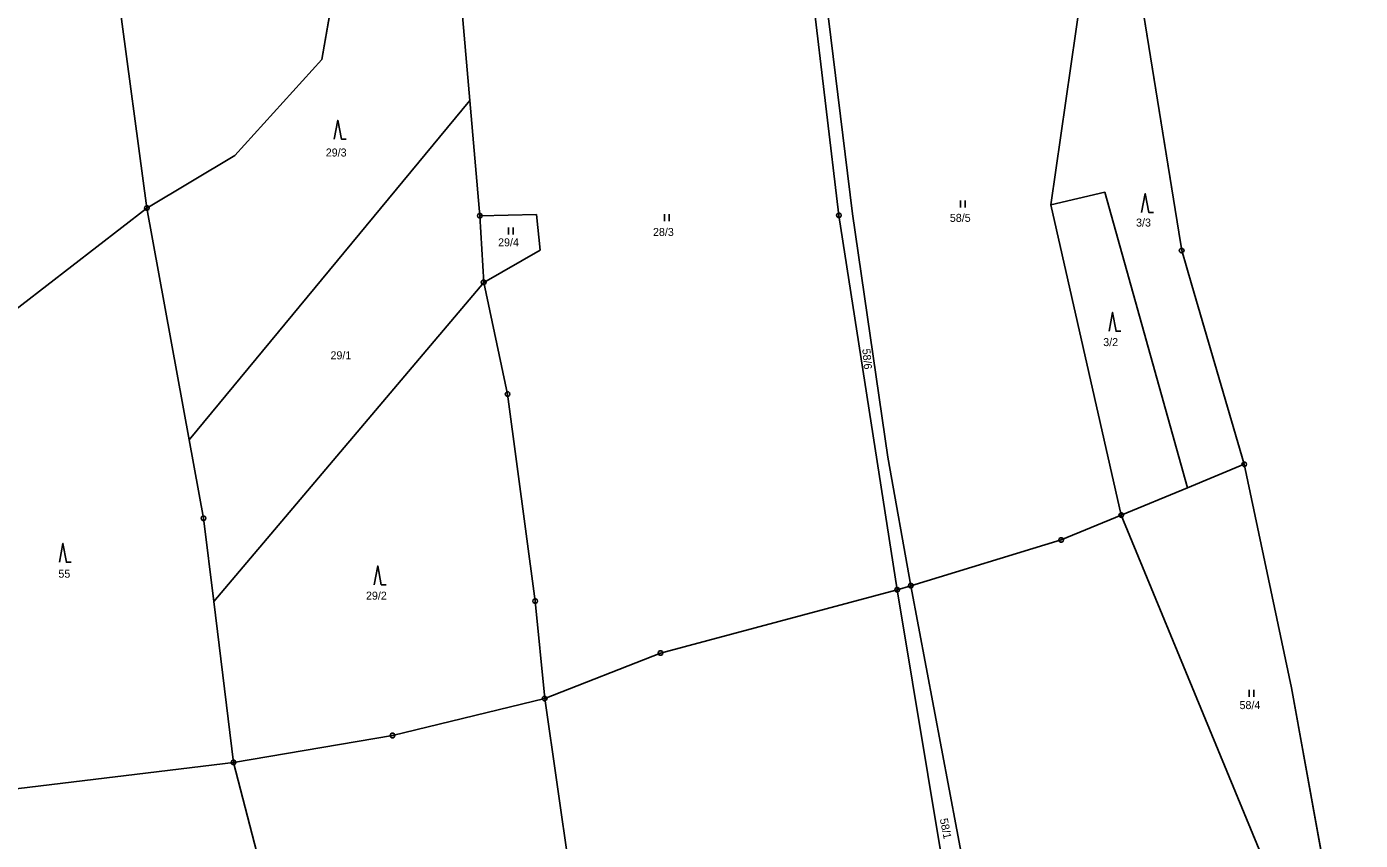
# Model space of a CAD drawing. Extents: x -580551 to -575069, y -1073031 to -1067931.
# Drawn here: x -576638.6 to -576355.3, y -1069440.4 to -1069267.5 of the extents above; entities that cross this region are included whole.
import ezdxf

# ---------------------------------------------------------------- set-up
doc = ezdxf.new("R2010")
doc.units = 0
for name, color, linetype in [('Druh pozemku', 7, 'Continuous'), ('Geodetické body', 7, 'Continuous'), ('Hranice obcí', 7, 'Continuous'), ('Hranice z DKM', 7, 'Continuous'), ('Katastrální hranice', 7, 'Continuous'), ('Parcela', 7, 'Continuous'), ('Parcelní číslo', 7, 'Continuous')]:
    doc.layers.add(name, color=color, linetype=linetype)

msp = doc.modelspace()

# ---------------------------------------------------------------- linework, layer by layer
at = {"layer": 'Druh pozemku'}
for p, q in [((-576440.24, -1069304.47), (-576440.24, -1069305.97)), ((-576439.24, -1069305.97), (-576439.24, -1069304.47)), ((-576503.17, -1069307.34), (-576503.17, -1069308.84)), ((-576502.17, -1069308.84), (-576502.17, -1069307.34)), ((-576536.3, -1069310.19), (-576536.3, -1069311.69)), ((-576535.3, -1069311.69), (-576535.3, -1069310.19)), ((-576378.97, -1069408.45), (-576378.97, -1069409.95)), ((-576377.97, -1069409.95), (-576377.97, -1069408.45))]:
    msp.add_line(p, q, dxfattribs=at)
for points in [[(-576573.28, -1069291.41), (-576572.53, -1069287.41), (-576571.78, -1069291.41), (-576570.78, -1069291.41)], [(-576401.78, -1069307), (-576401.03, -1069303), (-576400.28, -1069307), (-576399.28, -1069307)], [(-576408.71, -1069332.26), (-576407.96, -1069328.26), (-576407.21, -1069332.26), (-576406.21, -1069332.26)], [(-576631.67, -1069381.32), (-576630.92, -1069377.32), (-576630.17, -1069381.32), (-576629.17, -1069381.32)], [(-576564.79, -1069386.11), (-576564.04, -1069382.11), (-576563.29, -1069386.11), (-576562.29, -1069386.11)]]:
    msp.add_lwpolyline(points, dxfattribs=at)
at = {"layer": 'Geodetické body'}
for p, q in [((-576613.2, -1069306.06), (-576612.96, -1069306.06)), ((-576542.47, -1069307.7), (-576542.23, -1069307.7)), ((-576466.2, -1069307.62), (-576465.96, -1069307.62)), ((-576393.4, -1069315.11), (-576393.16, -1069315.11)), ((-576541.66, -1069321.86), (-576541.42, -1069321.86)), ((-576536.58, -1069345.6), (-576536.34, -1069345.6)), ((-576380.1, -1069360.52), (-576379.86, -1069360.52)), ((-576406.23, -1069371.32), (-576405.99, -1069371.32)), ((-576601.17, -1069371.99), (-576600.93, -1069371.99)), ((-576419, -1069376.59), (-576418.76, -1069376.59)), ((-576453.83, -1069387.19), (-576453.59, -1069387.19)), ((-576450.92, -1069386.31), (-576450.68, -1069386.31)), ((-576530.74, -1069389.59), (-576530.5, -1069389.59)), ((-576504.1, -1069400.63), (-576503.86, -1069400.63)), ((-576528.71, -1069410.32), (-576528.47, -1069410.32)), ((-576561.03, -1069418.15), (-576560.79, -1069418.15)), ((-576594.82, -1069423.88), (-576594.58, -1069423.88))]:
    msp.add_line(p, q, dxfattribs=at)
for points in [[(-576612.93, -1069305.58), (-576612.68, -1069305.76), (-576612.58, -1069306.05), (-576612.68, -1069306.34), (-576612.93, -1069306.52), (-576613.24, -1069306.52), (-576613.49, -1069306.34), (-576613.59, -1069306.05), (-576613.49, -1069305.76), (-576613.24, -1069305.58)], [(-576542.2, -1069307.22), (-576541.95, -1069307.4), (-576541.85, -1069307.69), (-576541.95, -1069307.98), (-576542.2, -1069308.16), (-576542.51, -1069308.16), (-576542.76, -1069307.98), (-576542.86, -1069307.69), (-576542.76, -1069307.4), (-576542.51, -1069307.22)], [(-576465.93, -1069307.14), (-576465.68, -1069307.32), (-576465.58, -1069307.61), (-576465.68, -1069307.9), (-576465.93, -1069308.08), (-576466.24, -1069308.08), (-576466.49, -1069307.9), (-576466.59, -1069307.61), (-576466.49, -1069307.32), (-576466.24, -1069307.14)], [(-576393.13, -1069314.63), (-576392.88, -1069314.81), (-576392.78, -1069315.1), (-576392.88, -1069315.39), (-576393.13, -1069315.57), (-576393.44, -1069315.57), (-576393.69, -1069315.39), (-576393.79, -1069315.1), (-576393.69, -1069314.81), (-576393.44, -1069314.63)], [(-576541.39, -1069321.38), (-576541.14, -1069321.56), (-576541.04, -1069321.85), (-576541.14, -1069322.14), (-576541.39, -1069322.32), (-576541.7, -1069322.32), (-576541.95, -1069322.14), (-576542.05, -1069321.85), (-576541.95, -1069321.56), (-576541.7, -1069321.38)], [(-576536.31, -1069345.12), (-576536.06, -1069345.3), (-576535.96, -1069345.59), (-576536.06, -1069345.88), (-576536.31, -1069346.06), (-576536.62, -1069346.06), (-576536.87, -1069345.88), (-576536.97, -1069345.59), (-576536.87, -1069345.3), (-576536.62, -1069345.12)], [(-576379.83, -1069360.04), (-576379.58, -1069360.22), (-576379.48, -1069360.51), (-576379.58, -1069360.8), (-576379.83, -1069360.98), (-576380.14, -1069360.98), (-576380.39, -1069360.8), (-576380.49, -1069360.51), (-576380.39, -1069360.22), (-576380.14, -1069360.04)], [(-576600.9, -1069371.51), (-576600.65, -1069371.69), (-576600.55, -1069371.98), (-576600.65, -1069372.27), (-576600.9, -1069372.45), (-576601.21, -1069372.45), (-576601.46, -1069372.27), (-576601.56, -1069371.98), (-576601.46, -1069371.69), (-576601.21, -1069371.51)], [(-576405.96, -1069370.84), (-576405.71, -1069371.02), (-576405.61, -1069371.31), (-576405.71, -1069371.6), (-576405.96, -1069371.78), (-576406.27, -1069371.78), (-576406.52, -1069371.6), (-576406.62, -1069371.31), (-576406.52, -1069371.02), (-576406.27, -1069370.84)], [(-576418.73, -1069376.11), (-576418.48, -1069376.29), (-576418.38, -1069376.58), (-576418.48, -1069376.87), (-576418.73, -1069377.05), (-576419.04, -1069377.05), (-576419.29, -1069376.87), (-576419.39, -1069376.58), (-576419.29, -1069376.29), (-576419.04, -1069376.11)], [(-576450.65, -1069385.83), (-576450.4, -1069386.01), (-576450.3, -1069386.3), (-576450.4, -1069386.59), (-576450.65, -1069386.77), (-576450.96, -1069386.77), (-576451.21, -1069386.59), (-576451.31, -1069386.3), (-576451.21, -1069386.01), (-576450.96, -1069385.83)], [(-576453.56, -1069386.71), (-576453.31, -1069386.89), (-576453.21, -1069387.18), (-576453.31, -1069387.47), (-576453.56, -1069387.65), (-576453.87, -1069387.65), (-576454.12, -1069387.47), (-576454.22, -1069387.18), (-576454.12, -1069386.89), (-576453.87, -1069386.71)], [(-576530.47, -1069389.11), (-576530.22, -1069389.29), (-576530.12, -1069389.58), (-576530.22, -1069389.87), (-576530.47, -1069390.05), (-576530.78, -1069390.05), (-576531.03, -1069389.87), (-576531.13, -1069389.58), (-576531.03, -1069389.29), (-576530.78, -1069389.11)], [(-576503.83, -1069400.15), (-576503.58, -1069400.33), (-576503.48, -1069400.62), (-576503.58, -1069400.91), (-576503.83, -1069401.09), (-576504.14, -1069401.09), (-576504.39, -1069400.91), (-576504.49, -1069400.62), (-576504.39, -1069400.33), (-576504.14, -1069400.15)], [(-576528.44, -1069409.84), (-576528.19, -1069410.02), (-576528.09, -1069410.31), (-576528.19, -1069410.6), (-576528.44, -1069410.78), (-576528.75, -1069410.78), (-576529, -1069410.6), (-576529.1, -1069410.31), (-576529, -1069410.02), (-576528.75, -1069409.84)], [(-576560.76, -1069417.67), (-576560.51, -1069417.85), (-576560.41, -1069418.14), (-576560.51, -1069418.43), (-576560.76, -1069418.61), (-576561.07, -1069418.61), (-576561.32, -1069418.43), (-576561.42, -1069418.14), (-576561.32, -1069417.85), (-576561.07, -1069417.67)], [(-576594.55, -1069423.4), (-576594.3, -1069423.58), (-576594.2, -1069423.87), (-576594.3, -1069424.16), (-576594.55, -1069424.34), (-576594.86, -1069424.34), (-576595.11, -1069424.16), (-576595.21, -1069423.87), (-576595.11, -1069423.58), (-576594.86, -1069423.4)]]:
    msp.add_lwpolyline(points, close=True, dxfattribs=at)
at = {"layer": 'Hranice obcí'}
msp.add_lwpolyline([(-576409.9, -1069008.03), (-576405.87, -1069042.84), (-576403.63, -1069055.64), (-576403.71, -1069058.31), (-576406.71, -1069154.32), (-576406.96, -1069167.755), (-576407.21, -1069181.19), (-576404.44, -1069197.86), (-576403.42, -1069206.69), (-576403.355, -1069214.295), (-576403.37, -1069238.77), (-576403.5, -1069248.93), (-576403.53, -1069251.55), (-576400.27, -1069271.75), (-576397.01, -1069291.95), (-576393.91, -1069311.22), (-576393.28, -1069315.11), (-576391.12, -1069322.48), (-576379.98, -1069360.52), (-576369.95, -1069408.04), (-576361.67, -1069453.73)], dxfattribs=at)
at = {"layer": 'Hranice z DKM'}
msp.add_line((-576412.78, -1069247.76), (-576421.07, -1069305.38), dxfattribs=at)
msp.add_lwpolyline([(-576551.9, -1069225.95), (-576567.01, -1069223.17), (-576575.94, -1069274.53), (-576594.44, -1069294.92)], dxfattribs=at)
at = {"layer": 'Katastrální hranice'}
for p, q in [((-576403.53, -1069251.55), (-576400.27, -1069271.75)), ((-576400.27, -1069271.75), (-576393.91, -1069311.22)), ((-576393.91, -1069311.22), (-576393.28, -1069315.11)), ((-576393.28, -1069315.11), (-576391.12, -1069322.48)), ((-576391.12, -1069322.48), (-576379.98, -1069360.52)), ((-576379.98, -1069360.52), (-576369.95, -1069408.04)), ((-576369.95, -1069408.04), (-576361.67, -1069453.73))]:
    msp.add_line(p, q, dxfattribs=at)
at = {"layer": 'Parcela'}
for p, q in [((-576575.94, -1069274.53), (-576567.01, -1069223.17)), ((-576544.49, -1069283.21), (-576549.47, -1069226.4)), ((-576475.2, -1069231.41), (-576466.08, -1069307.62)), ((-576463.19, -1069307.26), (-576472.39, -1069232.12)), ((-576620.89, -1069248.16), (-576613.08, -1069306.06)), ((-576421.07, -1069305.38), (-576412.78, -1069247.76)), ((-576594.44, -1069294.92), (-576575.94, -1069274.53)), ((-576604.09, -1069355.31), (-576544.49, -1069283.21)), ((-576542.35, -1069307.7), (-576544.49, -1069283.21)), ((-576613.08, -1069306.06), (-576594.44, -1069294.92)), ((-576421.07, -1069305.38), (-576409.57, -1069302.71)), ((-576409.57, -1069302.71), (-576392.03, -1069365.5)), ((-576645.78, -1069331.31), (-576613.08, -1069306.06)), ((-576613.08, -1069306.06), (-576604.09, -1069355.31)), ((-576406.11, -1069371.32), (-576421.07, -1069305.38)), ((-576542.35, -1069307.7), (-576530.36, -1069307.43)), ((-576541.54, -1069321.86), (-576542.35, -1069307.7)), ((-576530.36, -1069307.43), (-576529.58, -1069315.01)), ((-576466.08, -1069307.62), (-576453.71, -1069387.19)), ((-576455.68, -1069358.98), (-576463.19, -1069307.26)), ((-576529.58, -1069315.01), (-576541.54, -1069321.86)), ((-576541.54, -1069321.86), (-576598.88, -1069389.7)), ((-576536.46, -1069345.6), (-576541.54, -1069321.86)), ((-576530.62, -1069389.59), (-576536.46, -1069345.6)), ((-576604.09, -1069355.31), (-576601.05, -1069371.99)), ((-576450.8, -1069386.31), (-576455.68, -1069358.98)), ((-576392.03, -1069365.5), (-576379.98, -1069360.52)), ((-576406.11, -1069371.32), (-576392.03, -1069365.5)), ((-576418.88, -1069376.59), (-576406.11, -1069371.32)), ((-576355.33, -1069494.43), (-576406.11, -1069371.32)), ((-576601.05, -1069371.99), (-576598.88, -1069389.7)), ((-576450.8, -1069386.31), (-576418.88, -1069376.59)), ((-576503.98, -1069400.63), (-576453.71, -1069387.19)), ((-576453.71, -1069387.19), (-576450.8, -1069386.31)), ((-576453.71, -1069387.19), (-576443.95, -1069446.06)), ((-576427.24, -1069511.61), (-576450.8, -1069386.31)), ((-576598.88, -1069389.7), (-576594.7, -1069423.88)), ((-576528.59, -1069410.32), (-576530.62, -1069389.59)), ((-576528.59, -1069410.32), (-576503.98, -1069400.63)), ((-576560.91, -1069418.15), (-576528.59, -1069410.32)), ((-576515.07, -1069503.64), (-576528.59, -1069410.32)), ((-576594.7, -1069423.88), (-576560.91, -1069418.15)), ((-576663.35, -1069432.24), (-576594.7, -1069423.88)), ((-576594.7, -1069423.88), (-576558.42, -1069564.02))]:
    msp.add_line(p, q, dxfattribs=at)

# ---------------------------------------------------------------- texts
at = {"layer": 'Parcelní číslo'}
for s, p in [('29/3', (-576575.093, -1069295.11)), ('58/5', (-576442.527, -1069309)), ('3/3', (-576402.966, -1069310)), ('28/3', (-576505.586, -1069312)), ('29/4', (-576538.486, -1069314.2)), ('3/2', (-576409.945, -1069335.4)), ('29/1', (-576574.089, -1069338.21)), ('55', (-576631.889, -1069384.62)), ('29/2', (-576566.551, -1069389.28)), ('58/4', (-576380.996, -1069412.54))]:
    msp.add_text(s, height=1.7, dxfattribs=at).set_placement(p)
for s, rotation, p in [('58/6', 274.96245, (-576461.125, -1069336.013)), ('58/1', 281.43687, (-576444.672, -1069435.914))]:
    msp.add_text(s, height=1.7, rotation=rotation, dxfattribs=at).set_placement(p)

doc.saveas('drawing.dxf')
